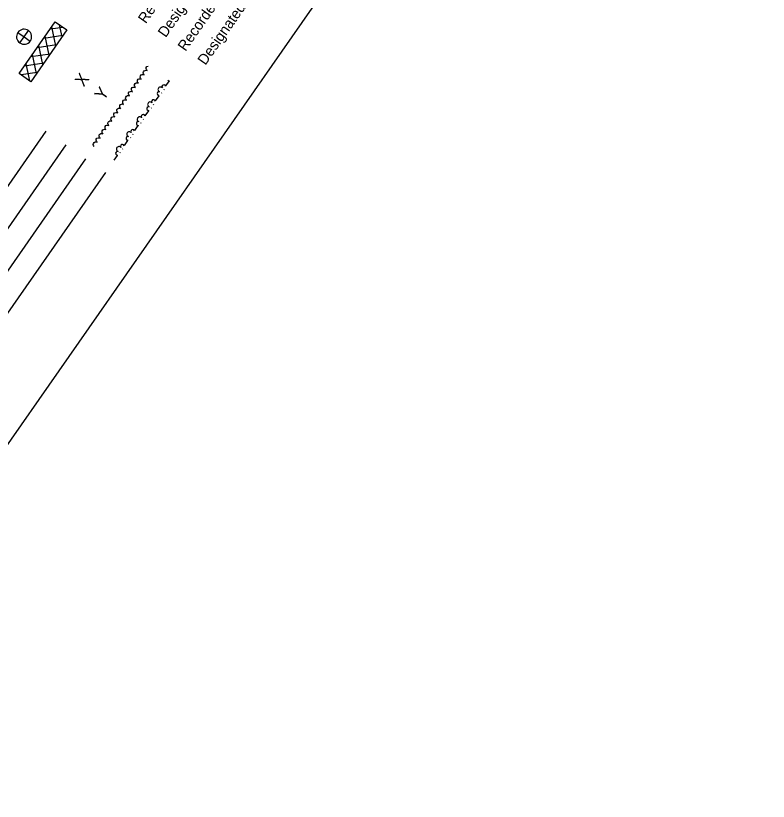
# Model space of a CAD drawing. Extents: x 1731327 to 1735374, y 884856 to 889832.
# Drawn here: x 1734752 to 1735374, y 888007 to 888656 of the extents above; entities that cross this region are included whole.
import ezdxf

# ---------------------------------------------------------------- set-up
doc = ezdxf.new("R2010")
doc.units = 0
doc.layers.add('Exist Utilities Telephone Pole CELL', color=7, linetype='Continuous')
doc.layers.add('Exist Vegetation Woods Line', color=7, linetype='Continuous')

msp = doc.modelspace()

# ---------------------------------------------------------------- linework, layer by layer
at = {"layer": 'Exist Utilities Telephone Pole CELL'}
msp.add_lwpolyline([(1734410.98, 887822.38), (1735374.4, 889202.95), (1734472.34, 889832.45), (1733508.91, 888451.88)], close=True, dxfattribs=at)
msp.add_lwpolyline([(1734410.98, 887822.38), (1735374.4, 889202.95), (1734472.34, 889832.45), (1733508.91, 888451.88)], close=True, dxfattribs=at)
at = {"layer": 'Exist Vegetation Woods Line'}
for p, q in [((1734755.13, 888608.31), (1734784.94, 888651.03)), ((1734784.94, 888651.03), (1734794.53, 888644.34)), ((1734759.16, 888638.76), (1734762.73, 888643.88)), ((1734794.53, 888644.34), (1734764.72, 888601.62)), ((1734791.46, 888646.48), (1734780.68, 888644.92)), ((1734785.32, 888631.14), (1734781.99, 888646.81)), ((1734790.61, 888638.72), (1734788.55, 888648.51)), ((1734754.03, 888642.34), (1734759.16, 888638.76)), ((1734755.58, 888633.63), (1734759.16, 888638.76)), ((1734759.16, 888638.76), (1734764.28, 888635.18)), ((1734791.27, 888639.66), (1734775.36, 888637.3)), ((1734780, 888623.51), (1734776.7, 888639.22)), ((1734785.95, 888632.04), (1734770.06, 888629.71)), ((1734774.68, 888615.89), (1734771.41, 888631.64)), ((1734780.63, 888624.41), (1734764.77, 888622.13)), ((1734769.39, 888608.3), (1734766.09, 888624.02)), ((1734775.34, 888616.83), (1734759.45, 888614.51)), ((1734763.78, 888602.28), (1734760.77, 888616.39)), ((1734858.31, 888610.62), (1734859.17, 888610.99)), ((1734859.17, 888610.99), (1734860.02, 888611.07)), ((1734860.02, 888611.07), (1734860.83, 888610.75)), ((1734860.11, 888612.42), (1734860.19, 888613.33)), ((1734860.3, 888611.55), (1734860.11, 888612.42)), ((1734860.19, 888613.33), (1734860.74, 888614.11)), ((1734860.9, 888610.76), (1734860.3, 888611.55)), ((1734860.74, 888614.11), (1734861.61, 888614.48)), ((1734861.61, 888614.48), (1734861.68, 888614.49)), ((1734764.72, 888601.62), (1734755.13, 888608.31)), ((1734755.62, 888607.97), (1734755.45, 888608.77)), ((1734770.02, 888609.2), (1734756.61, 888607.28)), ((1734855.24, 888605.45), (1734855.33, 888606.36)), ((1734855.43, 888604.58), (1734855.24, 888605.45)), ((1734855.33, 888606.36), (1734855.88, 888607.14)), ((1734856.04, 888603.79), (1734855.43, 888604.58)), ((1734855.88, 888607.14), (1734856.74, 888607.51)), ((1734856.74, 888607.51), (1734857.59, 888607.59)), ((1734857.59, 888607.59), (1734858.4, 888607.26)), ((1734857.67, 888608.93), (1734857.76, 888609.84)), ((1734857.86, 888608.07), (1734857.67, 888608.93)), ((1734857.76, 888609.84), (1734858.31, 888610.62)), ((1734858.47, 888607.28), (1734857.86, 888608.07)), ((1734850.38, 888598.48), (1734850.47, 888599.39)), ((1734850.57, 888597.61), (1734850.38, 888598.48)), ((1734850.47, 888599.39), (1734851.01, 888600.17)), ((1734851.01, 888600.17), (1734851.88, 888600.54)), ((1734851.88, 888600.54), (1734852.73, 888600.62)), ((1734852.73, 888600.62), (1734853.54, 888600.3)), ((1734852.81, 888601.96), (1734852.9, 888602.87)), ((1734853, 888601.1), (1734852.81, 888601.96)), ((1734852.9, 888602.87), (1734853.44, 888603.65)), ((1734853.61, 888600.31), (1734853, 888601.1)), ((1734853.44, 888603.65), (1734854.31, 888604.02)), ((1734854.31, 888604.02), (1734855.16, 888604.1)), ((1734855.16, 888604.1), (1734855.97, 888603.78)), ((1734876.44, 888598.09), (1734879.3, 888602.19)), ((1734845.52, 888591.51), (1734845.6, 888592.42)), ((1734845.71, 888590.64), (1734845.52, 888591.51)), ((1734845.6, 888592.42), (1734846.15, 888593.2)), ((1734846.15, 888593.2), (1734847.02, 888593.57)), ((1734847.02, 888593.57), (1734847.86, 888593.65)), ((1734847.86, 888593.65), (1734848.68, 888593.33)), ((1734847.95, 888594.99), (1734848.04, 888595.91)), ((1734848.14, 888594.13), (1734847.95, 888594.99)), ((1734848.04, 888595.91), (1734848.58, 888596.68)), ((1734848.74, 888593.34), (1734848.14, 888594.13)), ((1734848.58, 888596.68), (1734849.45, 888597.05)), ((1734849.45, 888597.05), (1734850.3, 888597.13)), ((1734850.3, 888597.13), (1734851.11, 888596.81)), ((1734851.18, 888596.82), (1734850.57, 888597.61)), ((1734872.82, 888592.02), (1734873.1, 888592.43)), ((1734874.82, 888594.89), (1734875.11, 888595.3)), ((1734840.65, 888584.54), (1734840.74, 888585.45)), ((1734840.74, 888585.45), (1734841.29, 888586.23)), ((1734841.29, 888586.23), (1734842.15, 888586.6)), ((1734842.15, 888586.6), (1734843, 888586.68)), ((1734843, 888586.68), (1734843.81, 888586.36)), ((1734843.08, 888588.02), (1734843.17, 888588.94)), ((1734843.27, 888587.16), (1734843.08, 888588.02)), ((1734843.17, 888588.94), (1734843.72, 888589.72)), ((1734843.88, 888586.37), (1734843.27, 888587.16)), ((1734843.72, 888589.72), (1734844.58, 888590.09)), ((1734844.58, 888590.09), (1734845.43, 888590.16)), ((1734845.43, 888590.16), (1734846.24, 888589.84)), ((1734846.31, 888589.85), (1734845.71, 888590.64)), ((1734867.86, 888585.79), (1734870.72, 888589.89)), ((1734835.88, 888578.48), (1734836.42, 888579.26)), ((1734836.42, 888579.26), (1734837.29, 888579.63)), ((1734837.29, 888579.63), (1734838.14, 888579.71)), ((1734838.14, 888579.71), (1734838.95, 888579.39)), ((1734838.22, 888581.05), (1734838.31, 888581.97)), ((1734838.41, 888580.19), (1734838.22, 888581.05)), ((1734838.31, 888581.97), (1734838.85, 888582.75)), ((1734839.02, 888579.4), (1734838.41, 888580.19)), ((1734838.85, 888582.75), (1734839.72, 888583.12)), ((1734839.72, 888583.12), (1734840.57, 888583.2)), ((1734840.57, 888583.2), (1734841.38, 888582.87)), ((1734840.84, 888583.67), (1734840.65, 888584.54)), ((1734841.45, 888582.89), (1734840.84, 888583.67)), ((1734864.24, 888579.72), (1734864.52, 888580.13)), ((1734866.24, 888582.59), (1734866.53, 888583)), ((1734831.01, 888571.51), (1734831.56, 888572.29)), ((1734831.56, 888572.29), (1734832.43, 888572.66)), ((1734832.43, 888572.66), (1734833.27, 888572.74)), ((1734833.27, 888572.74), (1734834.09, 888572.42)), ((1734833.36, 888574.09), (1734833.45, 888575)), ((1734833.55, 888573.22), (1734833.36, 888574.09)), ((1734833.45, 888575), (1734833.99, 888575.78)), ((1734834.15, 888572.43), (1734833.55, 888573.22)), ((1734833.99, 888575.78), (1734834.86, 888576.15)), ((1734834.86, 888576.15), (1734835.71, 888576.23)), ((1734835.71, 888576.23), (1734836.52, 888575.9)), ((1734835.79, 888577.57), (1734835.88, 888578.48)), ((1734835.98, 888576.71), (1734835.79, 888577.57)), ((1734836.59, 888575.92), (1734835.98, 888576.71)), ((1734859.28, 888573.49), (1734862.14, 888577.59)), ((1734826.7, 888565.32), (1734827.56, 888565.69)), ((1734827.56, 888565.69), (1734828.41, 888565.77)), ((1734828.41, 888565.77), (1734829.22, 888565.45)), ((1734828.49, 888567.12), (1734828.58, 888568.03)), ((1734828.68, 888566.25), (1734828.49, 888567.12)), ((1734828.58, 888568.03), (1734829.13, 888568.81)), ((1734829.29, 888565.46), (1734828.68, 888566.25)), ((1734829.13, 888568.81), (1734829.99, 888569.18)), ((1734829.99, 888569.18), (1734830.84, 888569.26)), ((1734830.84, 888569.26), (1734831.65, 888568.93)), ((1734830.93, 888570.6), (1734831.01, 888571.51)), ((1734831.12, 888569.74), (1734830.93, 888570.6)), ((1734831.72, 888568.95), (1734831.12, 888569.74)), ((1734855.65, 888567.43), (1734855.94, 888567.84)), ((1734857.66, 888570.3), (1734857.94, 888570.71)), ((1734777.25, 888560.77), (1734673.62, 888412.26)), ((1734823.63, 888560.15), (1734823.72, 888561.06)), ((1734823.82, 888559.28), (1734823.63, 888560.15)), ((1734823.72, 888561.06), (1734824.26, 888561.84)), ((1734824.43, 888558.49), (1734823.82, 888559.28)), ((1734824.26, 888561.84), (1734825.13, 888562.21)), ((1734825.13, 888562.21), (1734825.98, 888562.29)), ((1734825.98, 888562.29), (1734826.79, 888561.97)), ((1734826.06, 888563.63), (1734826.15, 888564.54)), ((1734826.25, 888562.77), (1734826.06, 888563.63)), ((1734826.15, 888564.54), (1734826.7, 888565.32)), ((1734826.86, 888561.98), (1734826.25, 888562.77)), ((1734850.7, 888561.19), (1734853.56, 888565.29)), ((1734818.77, 888553.18), (1734818.86, 888554.09)), ((1734818.96, 888552.31), (1734818.77, 888553.18)), ((1734818.86, 888554.09), (1734819.4, 888554.87)), ((1734819.4, 888554.87), (1734820.27, 888555.24)), ((1734820.27, 888555.24), (1734821.12, 888555.32)), ((1734821.12, 888555.32), (1734821.93, 888555)), ((1734821.2, 888556.66), (1734821.29, 888557.58)), ((1734821.39, 888555.8), (1734821.2, 888556.66)), ((1734821.29, 888557.58), (1734821.83, 888558.35)), ((1734822, 888555.01), (1734821.39, 888555.8)), ((1734821.83, 888558.35), (1734822.7, 888558.72)), ((1734822.7, 888558.72), (1734823.55, 888558.8)), ((1734823.55, 888558.8), (1734824.36, 888558.48)), ((1734842.11, 888548.9), (1734844.97, 888552.99)), ((1734847.07, 888555.13), (1734847.36, 888555.54)), ((1734849.07, 888558), (1734849.36, 888558.41)), ((1734793.64, 888549.32), (1734690.01, 888400.82)), ((1734816.34, 888549.69), (1734816.42, 888550.61)), ((1734816.53, 888548.83), (1734816.34, 888549.69)), ((1734816.42, 888550.61), (1734816.97, 888551.39)), ((1734817.13, 888548.04), (1734816.53, 888548.83)), ((1734816.97, 888551.39), (1734817.84, 888551.76)), ((1734817.84, 888551.76), (1734818.68, 888551.83)), ((1734818.68, 888551.83), (1734819.5, 888551.51)), ((1734819.56, 888551.52), (1734818.96, 888552.31)), ((1734840.49, 888545.7), (1734840.78, 888546.11)), ((1734833.53, 888536.6), (1734836.39, 888540.7)), ((1734838.49, 888542.83), (1734838.78, 888543.24)), ((1734810.04, 888537.88), (1734688.35, 888363.5)), ((1734826.44, 888526.44), (1734722.81, 888377.93))]:
    msp.add_line(p, q, dxfattribs=at)
for centre, radius, start, end in [((1734759.16, 888638.76), 6.25, 55.08545, 145.08998), ((1734759.16, 888638.76), 6.25, 325.08545, 55.08998), ((1734759.16, 888638.76), 6.25, 145.08545, 235.08998), ((1734759.16, 888638.76), 6.25, 235.08545, 325.08998), ((1734874.72, 888597.4), 1.58, 15.85954, 216.65611), ((1734879.3, 888603.96), 1.58, 211.34207, 258.84004), ((1734870.72, 888591.66), 1.58, 73.52601, 274.32258), ((1734871.9, 888595.1), 2.06, 41.05481, 249.1273), ((1734866.14, 888585.1), 1.58, 15.85954, 216.65611), ((1734862.13, 888579.36), 1.58, 73.52601, 274.32258), ((1734863.32, 888582.8), 2.06, 41.05481, 249.1273), ((1734854.73, 888570.5), 2.06, 41.05481, 249.1273), ((1734857.56, 888572.8), 1.58, 15.85954, 216.65611), ((1734853.55, 888567.06), 1.58, 73.52601, 274.32258), ((1734846.15, 888558.2), 2.06, 41.05481, 249.1273), ((1734848.97, 888560.5), 1.58, 15.85954, 216.65611), ((1734844.97, 888554.76), 1.58, 73.52601, 274.32258), ((1734837.57, 888545.91), 2.06, 41.05481, 249.1273), ((1734840.39, 888548.21), 1.58, 15.85954, 216.65611), ((1734836.39, 888542.47), 1.58, 73.52601, 274.32258)]:
    msp.add_arc(centre, radius, start, end, dxfattribs=at)

# ---------------------------------------------------------------- texts
for s, height, p in [('Designated U/G Telephone Conduit (S.U.E.*)', 8.7482, (1734876.22, 888637.57)), ('Designated U/G Fiber Optics Cable (S.U.E.*)', 8.7482, (1734909.02, 888614.69)), ('Recorded U/G Telephone Conduit', 8.7482, (1734859.82, 888649.02)), ('Recorded U/G Fiber Optics Cable', 8.7482, (1734892.62, 888626.13)), ('X', 10, (1734808.46, 888596.76)), ('Y', 10, (1734824.86, 888585.32))]:
    msp.add_text(s, height=height, rotation=55.09106, dxfattribs=at).set_placement(p)

doc.saveas('drawing.dxf')
